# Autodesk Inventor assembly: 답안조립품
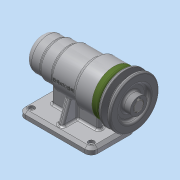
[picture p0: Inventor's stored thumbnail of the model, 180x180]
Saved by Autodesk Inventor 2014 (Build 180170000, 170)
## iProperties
Created: 2016-06
Part Number: 답안조립품
Document SubType Name: Assembly
Designer: dgall
Author: dgall
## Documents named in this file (12)
- C:\Users\dgall\Desktop\460607V1021\답안조립품.iam
- C:\Users\dgall\Desktop\460607V1021\V벨트풀리.ipt
- C:\Users\dgall\Desktop\460607V1021\멈춤나사 M3x8.ipt
- C:\Users\dgall\Desktop\460607V1021\베어링 6004.ipt
- C:\Users\dgall\Desktop\460607V1021\베어링 51202.ipt
- C:\Users\dgall\Desktop\460607V1021\본체.ipt
- C:\Users\dgall\Desktop\460607V1021\볼트 M4 x 12.ipt
- C:\Users\dgall\Desktop\460607V1021\어댑터슬리브.ipt
- C:\Users\dgall\Desktop\460607V1021\오일 실.ipt
- C:\Users\dgall\Desktop\460607V1021\축.ipt
- C:\Users\dgall\Desktop\460607V1021\커버.ipt
- C:\Users\dgall\Desktop\460607V1021\키 5 x 5 x 16.ipt
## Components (6 placed, 2 different names)
1. V벨트풀리:1
2. ISO 4762 M4 x 12:4
3. ISO 4762 M4 x 12:1
4. ISO 4762 M4 x 12:6
5. ISO 4762 M4 x 12:7
6. ISO 4762 M4 x 12:8
